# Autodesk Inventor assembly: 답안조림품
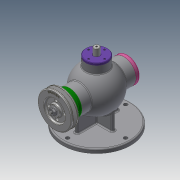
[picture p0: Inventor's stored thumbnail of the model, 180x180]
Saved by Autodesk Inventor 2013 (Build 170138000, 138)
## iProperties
Created: 2020-08
Part Number: 답안조림품
Document SubType Name: Assembly
Designer: 99
Author: 99
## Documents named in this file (17)
- C:\Users\user\Desktop\700806V1050\답안조림품.iam
- C:\Users\user\Desktop\거위\본체.ipt
- C:\Users\user\Desktop\거위\뒤커버.ipt
- C:\Users\user\Desktop\거위\베어링 6202.ipt
- 베어링 6202.ipt
- C:\Users\user\Desktop\거위\앞커버.ipt
- C:\Users\user\Desktop\거위\편심축.ipt
- C:\Users\user\Desktop\거위\슬라이드.ipt
- C:\Users\user\Desktop\거위\칼라.ipt
- C:\Users\user\Desktop\거위\멈춤링 15x1.ipt
- C:\Users\user\Desktop\거위\멈춤링 35x1.6.ipt
- 멈춤링 35x1.6.ipt
- C:\Users\user\Desktop\거위\V-벨트풀리.ipt
- C:\Users\user\Desktop\거위\볼트 M4.ipt
- C:\Users\user\Desktop\700806V1050\키 3x3x12.ipt
- C:\Users\user\Desktop\거위\상부커버.ipt
- C:\Users\user\Desktop\거위\너트 M8.ipt
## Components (1 placed, 1 different names)
1. V-벨트풀리:1
